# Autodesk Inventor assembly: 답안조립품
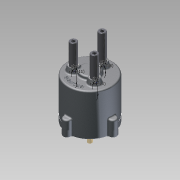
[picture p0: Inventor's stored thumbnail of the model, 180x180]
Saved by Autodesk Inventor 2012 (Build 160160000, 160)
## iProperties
Created: 2015-05
Part Number: 답안조립품
Document SubType Name: Assembly
Designer: Administrator
Author: Administrator
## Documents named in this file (14)
- C:\Inventor1급\2014-02-20 1급 공용부품\답안조립품.iam
- C:\Inventor1급\2014-02-20 1급 공용부품\몸체.ipt
- C:\Inventor1급\2014-02-20 1급 공용부품\커버.ipt
- C:\Inventor1급\2014-02-20 1급 공용부품\오일실.ipt
- C:\Inventor1급\2014-02-20 1급 공용부품\베어링 NA 4900.ipt
- C:\Inventor1급\2014-02-20 1급 공용부품\메인 축.ipt
- C:\Inventor1급\2014-02-20 1급 공용부품\멈춤링 22 x 1.2.ipt
- C:\Inventor1급\2014-02-20 1급 공용부품\판캠.ipt
- C:\Inventor1급\2014-02-20 1급 공용부품\슬라이드 축.ipt
- C:\Inventor1급\2014-02-20 1급 공용부품\가변 스프링-01.ipt
- C:\Inventor1급\2014-02-20 1급 공용부품\가변 스프링-02.ipt
- C:\Inventor1급\2014-02-20 1급 공용부품\가변 스프링-03.ipt
- C:\Inventor1급\2014-02-20 1급 공용부품\M5x0.5x20.ipt
- C:\Inventor1급\2014-02-20 1급 공용부품\멈춤링 10 x 1.ipt
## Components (7 placed, 4 different names)
1. 가변 스프링-01:1
2. 가변 스프링-02:1
3. 가변 스프링-03:1
4. M5x0.5x20:1
5. M5x0.5x20:2
6. M5x0.5x20:3
7. M5x0.5x20:4
